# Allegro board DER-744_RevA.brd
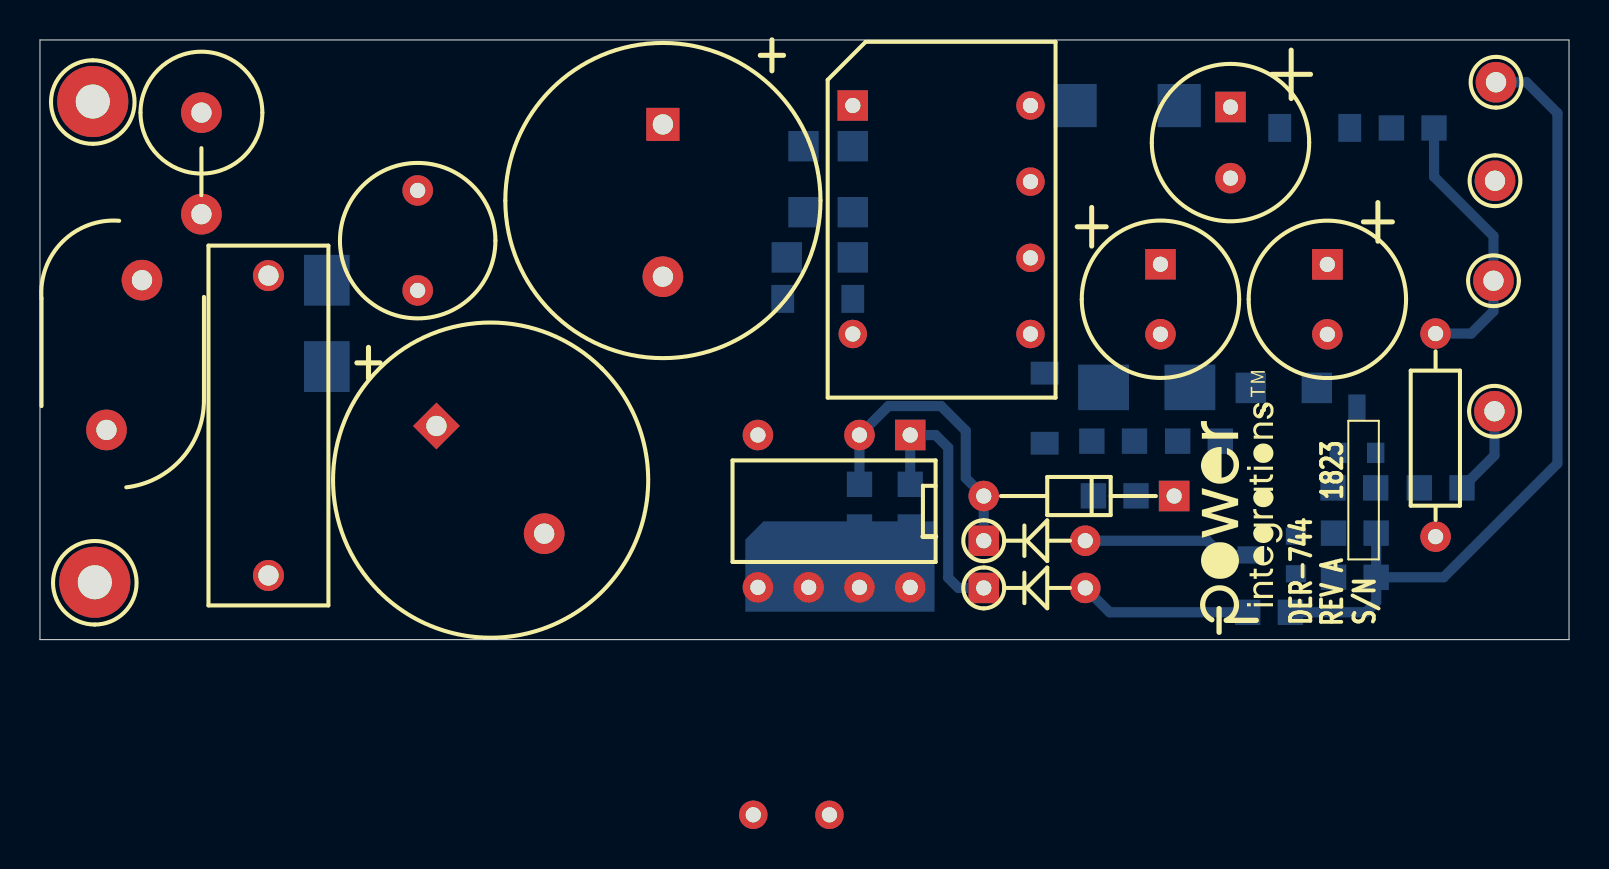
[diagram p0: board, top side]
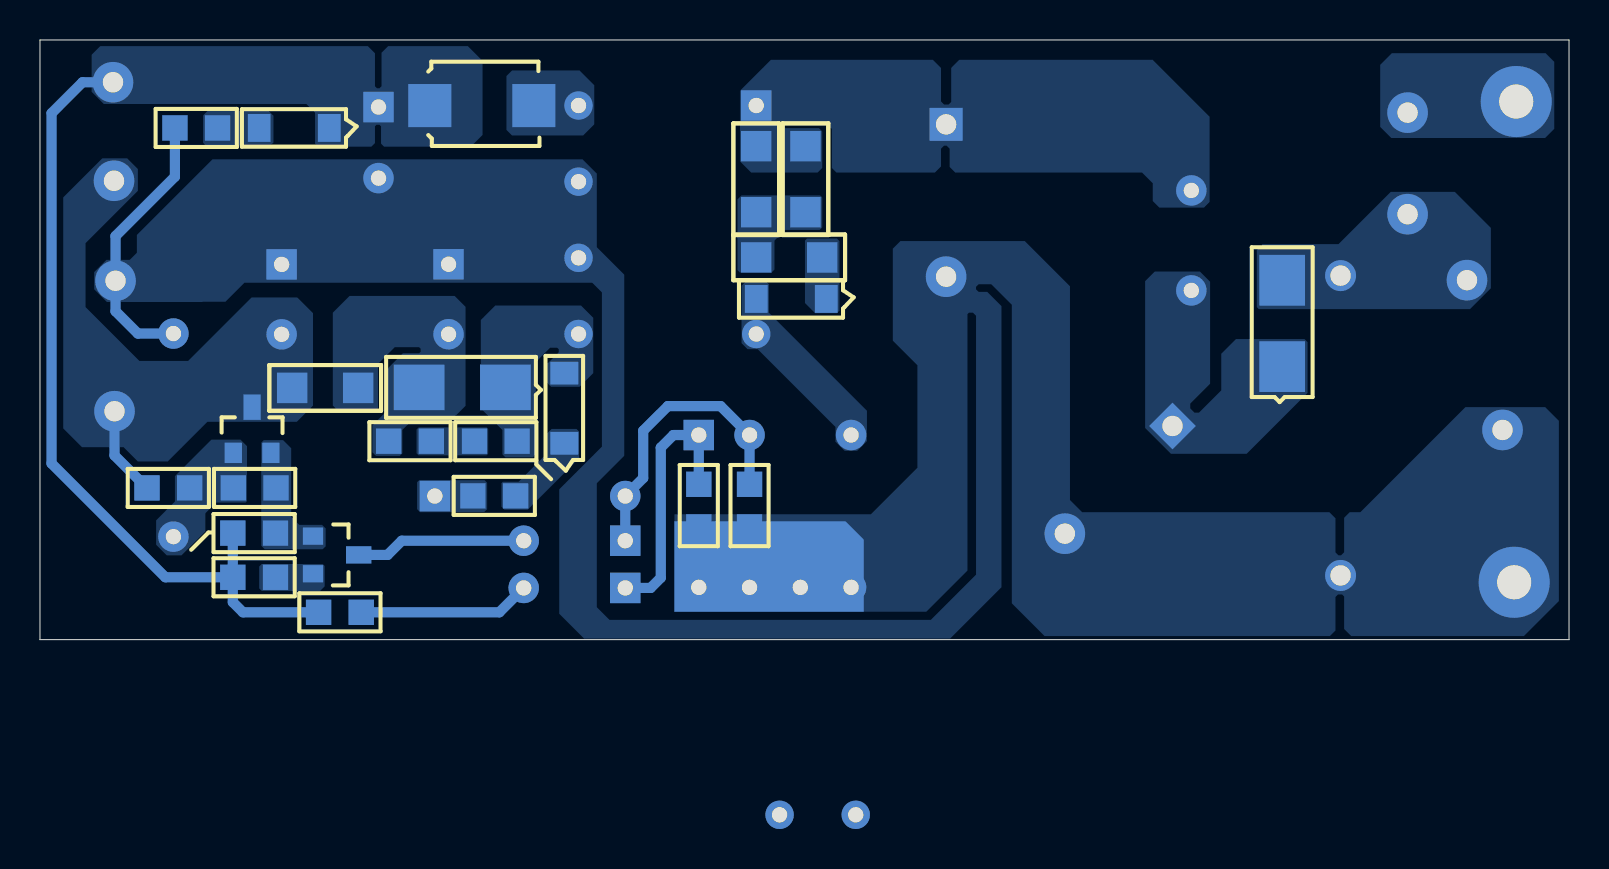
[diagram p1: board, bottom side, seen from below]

Outline 76.5 x 30 mm; copper layers: TOP, BOTTOM. Coordinates in mm from the lower left corner of the outline.
Outline path: 0,30 0,0 76.5,0 76.5,30 0,30

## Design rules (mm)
constraint set DEFAULT: min track width 0.508

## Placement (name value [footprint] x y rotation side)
C1  0.047 uF  [PINPCAPRAD18X6LS15MM040]  11.43 18.21 270 top
C2  18 uF  [PIPOLCAPCLYD630LS300040]  19.84 10.69 315 top
C3  18 uF  [PIPOLCAPCLYD630LS300040]  31.17 25.78 270 top
C4  1000 uF  [PIPOLCAPCLYD320LS140030]  59.56 26.64 270 top
C5  680 uF  [PI_POLCAP_D8H22LS3P5MMD030H]  56.06 17.03 270 top
C6  680 uF  [PI_POLCAP_D8H22LS3P5MMD030H]  64.41 17.02 270 top
C7  0.1 uF  [PISMC0805]  43.54 7.77 270 bottom
C8  100 pF  [PISMC1206]  40.67 24.68 270 bottom
C9  1.5 nF  [PISMC0805]  52.63 9.93 0 bottom
C10  10 nF  [PISMC0805]  64.69 7.59 0 bottom
C11  68 pf  [PISMC0805]  41 7.77 270 bottom
D1  GS1M-LTP  [PISMDO214AC12]  14.35 13.66 90 bottom
D2  SS2H10-E3/52T  [PISMSMB]  57 26.72 180 bottom
D3  SS26-E3/52T  [PISMDO214AC12]  53.21 12.62 0 bottom
D4  S1ML  [PI_SM_SOD-123_12]  37.16 17.05 0 bottom
D5  1N4148  [PIDV200X080X030DO35]  47.22 4.95 0 top
D6  1N4148  [PIDV200X080X030DO35]  47.22 2.59 0 top
D7  1N4148W RHG  [PI_SM_SOD-123_12]  50.27 9.83 90 bottom
GND  BLK  [PITPKEYSTONE100X100]  72.8 22.96 0 top
L1  47 uH  [PICHOKETOKINVD345H453LS197D030]  18.9 17.47 90 top
L2  50 Ohm @ 100MHz  [PISMR1206]  63.88 12.59 180 bottom
LINE  WHT  [PITPKEYSTONE125X125]  2.64 26.92 0 top
NEUTRAL  BLK  [PITPKEYSTONE125X125]  2.74 2.87 0 top
NOREF  -  []  0 0 90 top
NOREF#2  -  []  57.61 0.25 90 top
NOREF#3  -  []  0 30 0 top
Q1  MMBT3906  [PISMSOT23123_1]  62.84 3.3 270 bottom
R1  432 k  [PISMR1206]  38.2 24.68 270 bottom
R2  100  [PISMR0805]  67.61 25.6 0 bottom
R3  10  [PISMR0805]  56.92 9.93 0 bottom
R4  187 k  [PI14WVRESD100LS100D030]  69.82 5.15 90 top
R5  60.4 k  [PISMR0805]  69.01 7.59 0 bottom
R6  47  [PISMR0805]  66.85 3.12 180 bottom
R7  3.30 k  [PISMR0805]  66.85 5.33 180 bottom
R8  18 k  [PISMR0805]  62.56 1.37 180 bottom
R9  1 k  [PISMR0805]  52.7 7.19 0 bottom
R11  20  [PISMR1206]  37.36 19.12 0 bottom
RF1  4.7  [PI_2W_VRES240LS200D040]  8.08 26.37 270 top
RV1  385 Vac  [PI_DISC_530X315LS295X70D040]  5.11 17.98 270 top
T1  EF16  [PIBOBBINEF16V8P]  40.67 26.72 0 top
U1  LNK3696P  [PIICDIP8CSHORT5678]  43.54 10.24 180 top
U2  LMV431AIMF  [PISMSOT23132]  64.95 9.34 180 bottom
UNK5V_GND  BLK  [PITPKEYSTONE100X100]  72.77 11.43 90 top
UNK+5V  WHT  [PITPKEYSTONE100X100]  72.72 17.95 90 top
UNK+12V  YEL  [PITPKEYSTONE100X100]  72.85 27.89 0 top
VR2  MMSZ5239B-7-F  [PI_SM_SOD-123_12]  62.03 25.6 0 bottom
VR3  BZX79-C36,113  [PIDV200X080X030DO35#2]  56.74 7.18 180 top

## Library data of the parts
C1 C7-C11 = CAP NP
C2 C3 = CAP POL
C4 = CAP POL: alternate symbols: (pipolcapclyd320ls140d30h750)
C5 C6 = CAP POL: alternate symbols: (pi_polcap_d8ls3p5mmd030)
D1 D4 = DIODE
D2 = DIODE SCHOTTKY
D3 = DIODE SCHOTTKY: alternate symbols: (pismdo214ac12)
D5 D6 = DIODE: alternate symbols: (pidax375x070030do35,pidv100x080x030do35)
D7 = DIODE: alternate symbols: (pi_sm_sod-123_12_1)
GND LINE NEUTRAL UNK5V_GND UNK+5V UNK+12V = TESTPOINT
L1 = INDUCTOR
L2 = INDUCTOR_BEAD
Q1 = PNP_BEC
R1-R3 R5-R9 R11 = R
R4 = R: alternate symbols: (pi14wvresd100ls200d030,pi14wresd100ls400d030,pi14wresd100ls500d030)
RF1 = R: alternate symbols: (pi_2w_res6mmls15mmd040)
RV1 = VARISTOR: alternate symbols: (pi_np_ycap_rad540ls400d040_h,pi_2w_resd145ls455d040)
T1 = BEF16/8PINS/GENERIC
U1 = LNK3696
U2 = TL431/SOT-23_RCA
VR2 = DIODE_ZENER
VR3 = DIODE_ZENER: alternate symbols: (pidax375x070030do35)

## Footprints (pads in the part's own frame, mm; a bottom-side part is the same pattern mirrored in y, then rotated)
PI14WVRESD100LS100D030
  round 1.524 hole 0.762: 1(0,0) 2(10.16,0)
PI_2W_VRES240LS200D040
  round 2.032 hole 1.016: 1(0,0) 2(5.08,0)
PI_DISC_530X315LS295X70D040
  round 2.032 hole 1.016: 1(0,0) 2(7.493,-1.778)
PI_POLCAP_D8H22LS3P5MMD030H
  rect 1.524x1.524 hole 0.762: 1(-1.75,0)
  round 1.524 hole 0.762: 2(1.75,0)
PI_SM_SOD-123_12
  rect 1.143x1.397 smd: 1(0,0) 2(3.505,0)
PIBOBBINEF16V8P
  rect 1.524x1.524 hole 0.762: 1(0,0)
  round 1.422 hole 0.762: 2(-4.978,-35.484) 3(-1.168,-35.484) 4(0,-11.43) 5(8.891,-11.43) 6(8.891,-7.62) 7(8.891,-3.81) 8(8.891,0)
PICHOKETOKINVD345H453LS197D030
  round 1.524 hole 0.762: 1(0,0) 2(5.001,0)
PIDV200X080X030DO35
  rect 1.524x1.524 hole 0.762: 1(0,0)
  round 1.524 hole 0.762: 2(5.08,0)
PIDV200X080X030DO35#2
  rect 1.524x1.524 hole 0.762: 1(0,0)
  round 1.524 hole 0.762: 2(9.525,0)
PIICDIP8CSHORT5678
  rect 1.524x1.524 hole 0.762: 1(0,0)
  round 1.524 hole 0.762: 2(2.54,0) 4(7.62,0) 5(7.62,7.62) 6(5.08,7.62) 7(2.54,7.62) 8(0,7.62)
PINPCAPRAD18X6LS15MM040
  round 1.549 hole 1.016: 1(0,0) 2(15,0)
PIPOLCAPCLYD320LS140030
  rect 1.524x1.524 hole 0.762: 1(0,0)
  round 1.524 hole 0.762: 2(3.556,0)
PIPOLCAPCLYD630LS300040
  rect 1.651x1.651 hole 1.016: 1(0,0)
  round 2.032 hole 1.016: 2(7.62,0)
PISMC0805
  rect 1.27x1.27 smd: 1(0,0) 2(2.134,0)
PISMC1206
  rect 1.524x1.524 smd: 1(0,0) 2(3.302,0)
PISMDO214AC12
  rect 2.54x2.286 smd: 1(0,0) 2(4.318,0)
PISMR0805
  rect 1.27x1.27 smd: 1(0,0) 2(2.134,0)
PISMR1206
  rect 1.524x1.524 smd: 1(0,0) 2(3.302,0)
PISMSMB
  rect 2.159x2.159 smd: 1(0,0) 2(5.207,0)
PISMSOT23123_1
  rect 0.864x1.016 smd: 1(-1.88,0) 2(0,0)
  rect 0.864x1.27 smd: 3(-0.94,2.286)
PISMSOT23132
  rect 0.864x1.016 smd: 1(-1.88,0) 2(0,0)
  rect 0.864x1.27 smd: 3(-0.94,2.286)
PITPKEYSTONE100X100
  round 2.032 hole 1.016: 1(0,0)
PITPKEYSTONE125X125
  round 3.556 hole 1.702: 1(0,0)

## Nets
N00739: C7.1 D6.1 U1.1
N00834: D4.2 T1.4 U1.4
N00928: C3.1 C8.1 L1.2 R1.1 T1.1
N01202: C8.2 R1.2 R11.2
N01422: C2.1 D1.1 L1.1
N01526: C1.2 C2.2 C3.2 C4.2 C5.1 C6.1 C7.2 C11.2 NEUTRAL.1 R2.2 R4.2 RV1.2 T1.6 T1.7 U1.5 U1.6 U1.7 U1.8(S8) UNK+5V.1
N01677: C1.1 D1.2 RF1.2 RV1.1
N02556: LINE.1 RF1.1
N02791: C4.1 D2.1 R6.1 R7.1 R8.1 UNK+12V.1 VR2.1
N02906: C9.2 R3.1
N02910: C5.2 D3.2 L2.2 R3.2
N02953: C9.1 D3.1 D7.2 T1.5
N03528: C6.2 GND.1 L2.1 R5.2 U2.3 UNK5V_GND.1
N03748: R2.1 VR2.2
N05482: C10.1 Q1.1 R7.2 U2.2
N05581: C10.2 R4.1 R5.1 U2.1(VREF)
N08747: Q1.2(EMITTER) R6.2
N09276: C11.1 D5.1 U1.2 VR3.2
N12197: D5.2 Q1.3
N18239: D6.2 R8.2
N20828: D2.2 T1.8
N26989: D4.1 R11.1
N098591: D7.1 R9.1
N100431: R9.2 VR3.1

Pads without a net: T1 2 3

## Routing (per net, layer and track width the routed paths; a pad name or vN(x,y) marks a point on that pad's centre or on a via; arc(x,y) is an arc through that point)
N00739: length 13.1
  BOTTOM w0.508: C7.1 U1.1 44.81,10.24 45.44,9.61 45.44,3.09 45.95,2.59 D6.1
N01526: length 13.8
  BOTTOM w0.508: R4.2 71.6,15.31 72.72,16.43 UNK+5V.1 72.72,20.19 69.75,23.16 R2.2
N02791: length 40.6
  BOTTOM w0.508: R6.1 66.85,1.88 66.34,1.37 R8.1 ; R6.1 70.23,3.12 75.92,8.81 75.92,26.34 74.37,27.89 UNK+12V.1 ; R6.1 R7.1
N03528: length 4.5
  BOTTOM w0.508: R5.2 72.77,9.22 UNK5V_GND.1
N09276: length 14.8
  BOTTOM w0.508: C11.1 U1.2 42.45,11.68 45.09,11.68 46.32,10.45 46.32,8.08 VR3.2 D5.1
N12197: length 8.5
  BOTTOM w0.508: Q1.3 59.11,4.24 58.4,4.95 D5.2
N18239: length 8.6
  BOTTOM w0.508: D6.2 53.52,1.37 R8.2

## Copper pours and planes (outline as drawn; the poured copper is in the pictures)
N00834 on BOTTOM: 41.22,17.88 40.13,17.88 40.03,17.78 40.03,16.36 35.13,11.46 35.13,9.93 35.61,9.45 36.25,9.45 36.7,9.91 36.7,10.64 40.59,14.53 41.1,14.53 41.4,14.83 41.4,17.7
N00928 on BOTTOM: 17.98,21.89 17.98,26.16 20.83,29.01 30.51,29.01 30.91,28.6 30.91,26.9 31.04,26.77 31.27,26.77 31.42,26.92 31.42,28.6 31.83,29.01 39.93,29.01 41.48,27.46 41.48,23.93 40.92,23.37 37.59,23.37 37.36,23.6 37.36,25.43 37.53,25.59 39.54,25.59 39.62,25.68 39.62,25.86 39.55,25.93 37.26,25.93 36.88,25.55 36.88,23.6 36.65,23.37 31.72,23.37 31.42,23.67 31.42,24.56 31.27,24.71 31.14,24.71 30.99,24.56 30.99,23.65 30.71,23.37 21.36,23.37 20.83,22.83 20.83,21.95 20.5,21.62 18.26,21.62
N01202 on BOTTOM: 41.61,22.02 41.61,18.49 41.48,18.36 39.9,18.36 39.75,18.52 39.75,19.96 39.22,20.5 37.49,20.5 37.36,20.62 37.36,22.12 37.47,22.23 41.4,22.23
N01422 on BOTTOM: 18.52,11.35 18.73,11.35 18.95,11.57 18.95,11.81 17.96,12.8 17.96,17.91 18.47,18.41 20.73,18.41 21.21,17.93 21.21,10.59 19.91,9.3 16.13,9.3 13.08,12.34 13.08,14.88 13.23,15.04 16.66,15.04 17.4,14.3 17.4,12.47
N01526 on BOTTOM (solid shape): 44.76,1.4 35.28,1.4 35.28,5 36.2,5.92 44.76,5.92
N01526 on BOTTOM: 0.51,10.95 1.19,11.63 5.18,11.63 10.44,6.38 10.97,6.38 11.25,6.1 11.25,4.37 11.4,4.22 11.53,4.22 11.68,4.37 11.68,6.07 11.99,6.38 24.36,6.38 24.97,6.99 24.97,17.68 27.23,19.94 33.45,19.94 33.83,19.56 33.83,14.96 32.6,13.73 32.6,8.6 34.92,6.27 44.75,6.27 44.75,1.4 32.16,1.4 30.1,3.45 30.1,16.28 30.02,16.36 29.82,16.36 29.67,16.21 29.67,3.25 31.93,0.99 48.01,0.99 48.64,1.63 48.64,7.82 47.27,9.19 47.27,18.26 48.64,19.63 48.64,23.32 49.35,24.03 67.87,24.03 71.65,20.24 71.65,19.35 72.01,19 73.18,19 73.79,18.39 73.79,17.53 73.15,16.89 68.38,16.89 68.36,16.9 67.22,16.9 66.27,17.86 48.87,17.86 48.39,17.37 48.39,9.65 50.52,7.52 50.52,1.3 49.28,0.05 30.96,0.05 28.4,2.62 28.4,16.69 29.11,17.4 29.54,17.4 29.67,17.53 29.67,17.65 29.54,17.78 28.91,17.78 27.88,16.75 27.88,1.82 26.24,0.18 11.96,0.18 11.68,0.46 11.68,2.13 11.56,2.26 11.35,2.26 11.25,2.16 11.25,0.53 10.9,0.18 2.26,0.18 0.51,1.93
N01677 on BOTTOM: 3.91,17.58 3.91,20.6 5.71,22.4 8.92,22.4 11.53,19.79 15.34,19.79 15.62,19.51 15.62,16.64 15.52,16.54 4.95,16.54
N02556 on BOTTOM: 1.17,29.34 8.86,29.34 9.45,28.75 9.45,25.65 8.89,25.1 1.19,25.1 0.74,25.55 0.74,28.91
N02791 on BOTTOM: 59.28,24.66 59.44,24.82 59.44,25.68 59.51,25.76 59.66,25.76 59.74,25.68 59.74,24.84 59.92,24.66 62.59,24.66 62.74,24.82 62.74,26.37 63.17,26.8 73.3,26.8 73.91,27.41 73.91,29.26 73.48,29.69 60.1,29.69 59.74,29.34 59.74,27.69 59.64,27.58 59.51,27.58 59.41,27.69 59.41,29.36 59.08,29.69 55.09,29.69 54.36,28.96 54.36,25.25 54.94,24.66
N02906 on BOTTOM: 57.56,10.62 54.15,10.62 54.08,10.54 54.08,9.3 54.15,9.22 57.56,9.22 57.66,9.32 57.66,10.52
N02910 on BOTTOM: 58.37,9.32 58.37,10.49 57.66,11.2 55.7,11.2 55.21,11.7 55.21,16.65 55.75,17.2 61.01,17.2 61.85,16.36 61.85,11.71 61.49,11.35 59.82,11.35 59.59,11.58 59.59,13.79 58.75,14.63 57.53,14.63 57.45,14.55 57.45,14.4 57.53,14.33 58.34,14.33 59.11,13.56 59.11,11.48 59.87,10.72 59.87,9.37 59.69,9.19 58.5,9.19
N02953 on BOTTOM: 48.82,13.34 49.5,12.65 50.93,12.65 51.18,12.9 51.18,13.74 50.55,14.38 50.55,14.53 50.62,14.61 50.98,14.61 51.69,13.89 51.69,9.27 51.84,9.12 53.21,9.12 53.37,9.27 53.37,10.49 54.46,11.58 54.46,13.72 54.44,13.73 54.44,15.99 53.72,16.71 49.43,16.71 48.82,16.1
N03528 on BOTTOM: 68.12,10.9 70.1,8.92 71.6,8.92 72.31,9.63 74.4,9.63 75.34,10.57 75.34,22.12 73.38,24.08 72.14,24.08 71.6,23.55 71.6,22.45 74.22,19.84 74.22,16.64 71.53,13.94 69.09,13.94 65.91,17.12 63.63,17.12 62.84,16.33 62.84,11.71 63.65,10.9
N03748 on BOTTOM: 66.95,26.47 66.94,26.45 65.06,26.45 64.82,26.21 64.82,24.87 64.97,24.71 68.2,24.71 68.34,24.85 68.34,26.23 68.1,26.47
N05482 on BOTTOM: 62.36,4.52 65.25,4.52 65.43,4.7 65.43,9.86 65.3,9.98 64.34,9.98 63.93,9.58 63.93,6.15 63.53,5.74 62.38,5.74 62.2,5.56 62.2,4.67
N05581 on BOTTOM: 66.14,6.93 66.14,9.68 66.47,10.01 67.92,10.01 69.75,8.18 69.75,6.91 70.69,5.97 70.69,4.75 70.15,4.22 69.42,4.22 68.22,5.41 68.22,6.32 67.69,6.86 66.22,6.86
N08747 on BOTTOM: 65.41,3.78 62.36,3.78 62.26,3.68 62.26,2.67 62.48,2.44 65.41,2.44 65.53,2.57 65.53,3.66
N20828 on BOTTOM: 48.77,25.78 49.33,25.22 52.88,25.22 53.16,25.5 53.16,28.19 52.88,28.47 49.5,28.47 48.77,27.74
N26989 on BOTTOM: 36.5,16.46 36.63,16.33 37.72,16.33 38.23,16.84 38.23,19.96 38.13,20.07 36.63,20.07 36.5,19.94
N098591 on BOTTOM: 49.53,10.41 49.53,9.07 52.1,6.5 53.26,6.5 53.42,6.65 53.42,7.82 53.34,7.9 52.55,7.9 51.1,9.35 51.1,10.34 50.9,10.54 49.66,10.54
N100431 on BOTTOM: 54.25,7.98 54.13,7.85 54.13,6.53 54.28,6.38 57.48,6.38 57.63,6.53 57.63,7.87 57.53,7.98

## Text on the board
Ref Des/Silkscreen Top: DER-744 | 1823 | REV A | S/N
User.5: DELETE THESE HOLES: | 1.  THROUGH HOLES ARE PLATED THROUGH. | EXCEPTIONS WILL BE NOTED IN DRILL CHART "NOTE". | 2.  MATERIAL: BASE MATERIAL LAMINATED EPOXY | UL APPROVED MANUFACTURED SOURCE FOR FR4. | 3.  SOLDER PLATE WILL BE RoHS COMPLIANT. | 4.  SOLDER MASK LPI (LIQUID PHOTO IMAGEABLE) BOTH SIDES. COLOR GREEN. | SOLDER MASK (REGISTRATION) -0/+0.003" | 5.  SILKSCREEN TOP/BOTTOM SIDE. COLOR WHITE. (MIN.WIDTH 0.005" MAX.WIDTH 0.010") | 6.  FINISH TO BE SMOBC. | 7.  LEAD FREE HASL (HOT AIR SOLDER LEVEL) OR RoHS COMPLIANT. | 8.  BOARD DIMENSION +/- 0.005" | 9.  DRILL TOLERANCE +/- 0.003" | 10. TRACE WIDTH UNDER 0.010" +/- 0.002" | TRACE WIDTH OVER 0.011" +/- 0.005" | 11. TRACE SPACE +/- 0.003" | 12. MATERIAL FR4 COPPER 1 OZ BOARD THICKNESS 0.062" | NOTES: UNLESS OTHERWISE SPECIFIED
User.8: FIGURE | FINISHED_SIZE | 30.0 | 40.0 | 67.0 | DRILL CHART: TOP to BOTTOM | ALL UNITS ARE IN MILS | PLATED | QTY | 31 | 14 | 2
